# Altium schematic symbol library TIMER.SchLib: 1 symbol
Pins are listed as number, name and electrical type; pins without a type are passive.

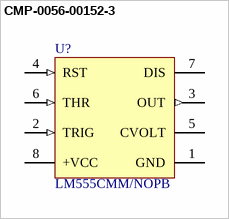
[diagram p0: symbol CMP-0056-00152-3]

## CMP-0056-00152-3
designator U?, comment LM555CMM/NOPB
Timer, 8-pin Mini SOIC, Pb-Free; Manufacturer: Texas Instruments; CompType: Analog IC; PowerWise: N; PackageTopMarking: ZXTT*Z55
footprint DGK0008A_M (TSOP, 8-Leads, Body 3.1x3.1mm, Pitch 0.65mm, IPC Low Density)
footprint DGK0008A_L (TSOP, 8-Leads, Body 3.1x3.1mm, Pitch 0.65mm, IPC High Density)
footprint DGK0008A_N (TSOP, 8-Leads, Body 3.1x3.1mm, Pitch 0.65mm, IPC Medium Density)
pins: 1 GND (power), 2 TRIG (in), 3 OUT (out), 4 RST (in), 5 CVOLT, 6 THR (in), 7 DIS (oc), 8 +VCC (power)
